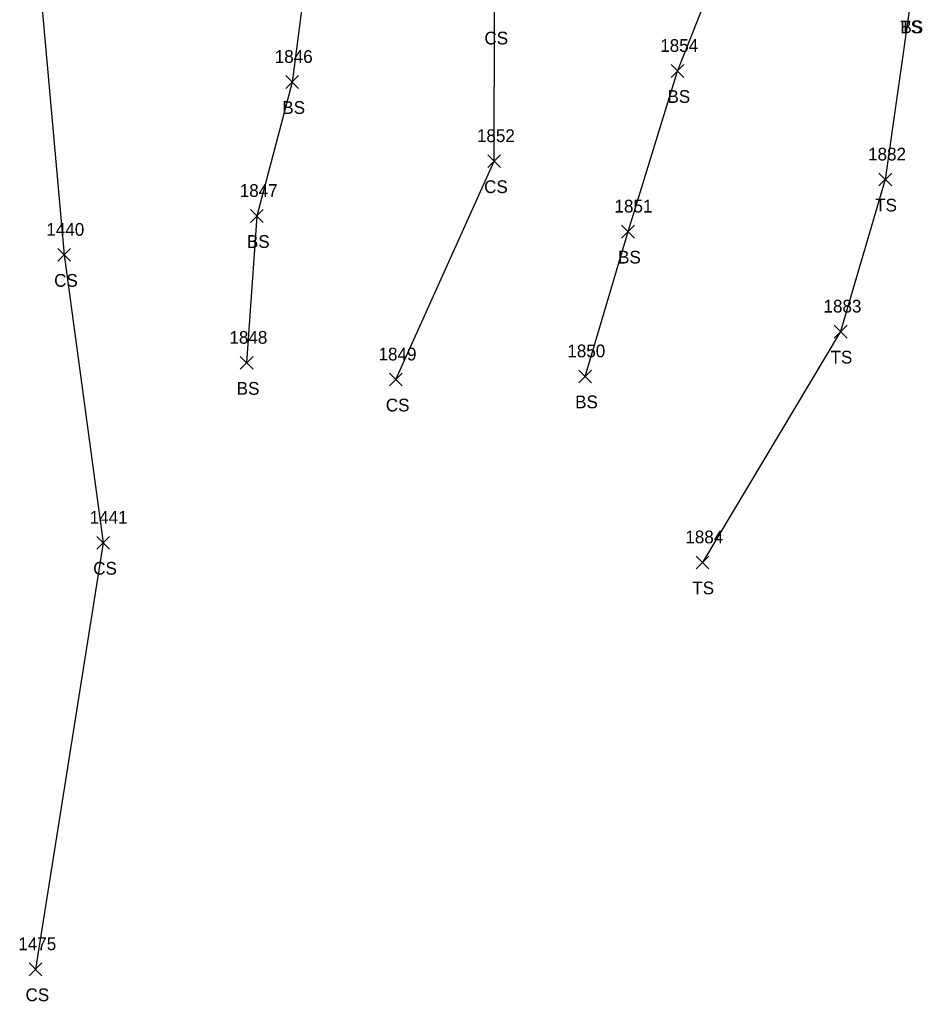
# Model space of a CAD drawing. Extents: x 1551995 to 1555700, y 777276 to 783130.
# Drawn here: x 1554978.7 to 1555120.3, y 777466.1 to 777620.1 of the extents above; entities that cross this region are included whole.
import ezdxf

# ---------------------------------------------------------------- set-up
doc = ezdxf.new("R2010")
doc.units = 0
for name, color, linetype in [('L_A', 7, 'Continuous'), ('L_I', 7, 'Continuous'), ('L_TIC', 7, 'Continuous'), ('LELB', 7, 'Continuous')]:
    doc.layers.add(name, color=color, linetype=linetype)

msp = doc.modelspace()

# ---------------------------------------------------------------- linework, layer by layer
at = {"layer": 'L_TIC'}
for points in [[(1555080.9, 777611.07), (1555082.9, 777613.07)], [(1555082.9, 777611.07), (1555080.9, 777613.07)], [(1555020.46, 777609.34), (1555022.46, 777611.34)], [(1555022.46, 777609.34), (1555020.46, 777611.34)], [(1555052.13, 777596.92), (1555054.13, 777598.92)], [(1555054.13, 777596.92), (1555052.13, 777598.92)], [(1555113.53, 777594.03), (1555115.53, 777596.03)], [(1555115.53, 777594.03), (1555113.53, 777596.03)], [(1555014.91, 777588.32), (1555016.91, 777590.32)], [(1555016.91, 777588.32), (1555014.91, 777590.32)], [(1555073.15, 777585.87), (1555075.15, 777587.87)], [(1555075.15, 777585.87), (1555073.15, 777587.87)], [(1554984.65, 777582.22), (1554986.65, 777584.22)], [(1554986.65, 777582.22), (1554984.65, 777584.22)], [(1555106.52, 777570.18), (1555108.52, 777572.18)], [(1555108.52, 777570.18), (1555106.52, 777572.18)], [(1555013.3, 777565.28), (1555015.3, 777567.28)], [(1555015.3, 777565.28), (1555013.3, 777567.28)], [(1555036.7, 777562.66), (1555038.7, 777564.66)], [(1555038.7, 777562.66), (1555036.7, 777564.66)], [(1555066.41, 777563.16), (1555068.41, 777565.16)], [(1555068.41, 777563.16), (1555066.41, 777565.16)], [(1554990.78, 777537.05), (1554992.78, 777539.05)], [(1554992.78, 777537.05), (1554990.78, 777539.05)], [(1555084.84, 777533.97), (1555086.84, 777535.97)], [(1555086.84, 777533.97), (1555084.84, 777535.97)], [(1554980.16, 777470.14), (1554982.16, 777472.14)], [(1554982.16, 777470.14), (1554980.16, 777472.14)]]:
    msp.add_lwpolyline(points, dxfattribs=at)
at = {"layer": 'LELB'}
for points in [[(1555088.61, 777716.24), (1555096.46, 777696.69), (1555101.68, 777679.67), (1555104.15, 777652.17), (1555118.46, 777622.99), (1555114.53, 777595.03), (1555107.52, 777571.18), (1555085.84, 777534.97)], [(1555067.41, 777564.16), (1555074.15, 777586.87), (1555081.9, 777612.07), (1555091.91, 777637.29), (1555090.07, 777660.1), (1555086.22, 777680.96), (1555077.02, 777704.11)], [(1555037.7, 777563.66), (1555053.13, 777597.92), (1555053.18, 777621.24), (1555049.57, 777652.82), (1555048.8, 777665.7)], [(1555031.47, 777662.83), (1555024.97, 777637.3), (1555021.46, 777610.34), (1555015.91, 777589.32), (1555014.3, 777566.28)], [(1554982.59, 777653.45), (1554981.81, 777626.54), (1554985.65, 777583.22), (1554991.78, 777538.05), (1554981.16, 777471.14)]]:
    msp.add_lwpolyline(points, dxfattribs=at)

# ---------------------------------------------------------------- texts
at = {"layer": 'L_A'}
for s, p in [('TS', (1555116.87, 777617.99)), ('BS', (1555116.9, 777617.99)), ('CS', (1555051.62, 777616.24)), ('BS', (1555080.34, 777607.07)), ('BS', (1555019.9, 777605.34)), ('CS', (1555051.57, 777592.92)), ('TS', (1555112.94, 777590.03)), ('BS', (1555014.35, 777584.32)), ('BS', (1555072.59, 777581.87)), ('CS', (1554984.09, 777578.22)), ('TS', (1555105.93, 777566.18)), ('BS', (1555012.74, 777561.28)), ('BS', (1555065.85, 777559.16)), ('CS', (1555036.14, 777558.66)), ('CS', (1554990.22, 777533.05)), ('TS', (1555084.25, 777529.97)), ('CS', (1554979.6, 777466.14))]:
    msp.add_text(s, height=2, dxfattribs=at).set_placement(p)
at = {"layer": 'L_I'}
for s, p in [('1854', (1555079.21, 777615.07)), ('1846', (1555018.71, 777613.34)), ('1852', (1555050.44, 777600.92)), ('1882', (1555111.83, 777598.03)), ('1847', (1555013.22, 777592.32)), ('1851', (1555072.03, 777589.87)), ('1440', (1554982.87, 777586.22)), ('1883', (1555104.83, 777574.18)), ('1848', (1555011.6, 777569.28)), ('1849', (1555035, 777566.66)), ('1850', (1555064.63, 777567.16)), ('1441', (1554989.66, 777541.05)), ('1884', (1555083.15, 777537.97)), ('1475', (1554978.47, 777474.14))]:
    msp.add_text(s, height=2, dxfattribs=at).set_placement(p)

doc.saveas('drawing.dxf')
